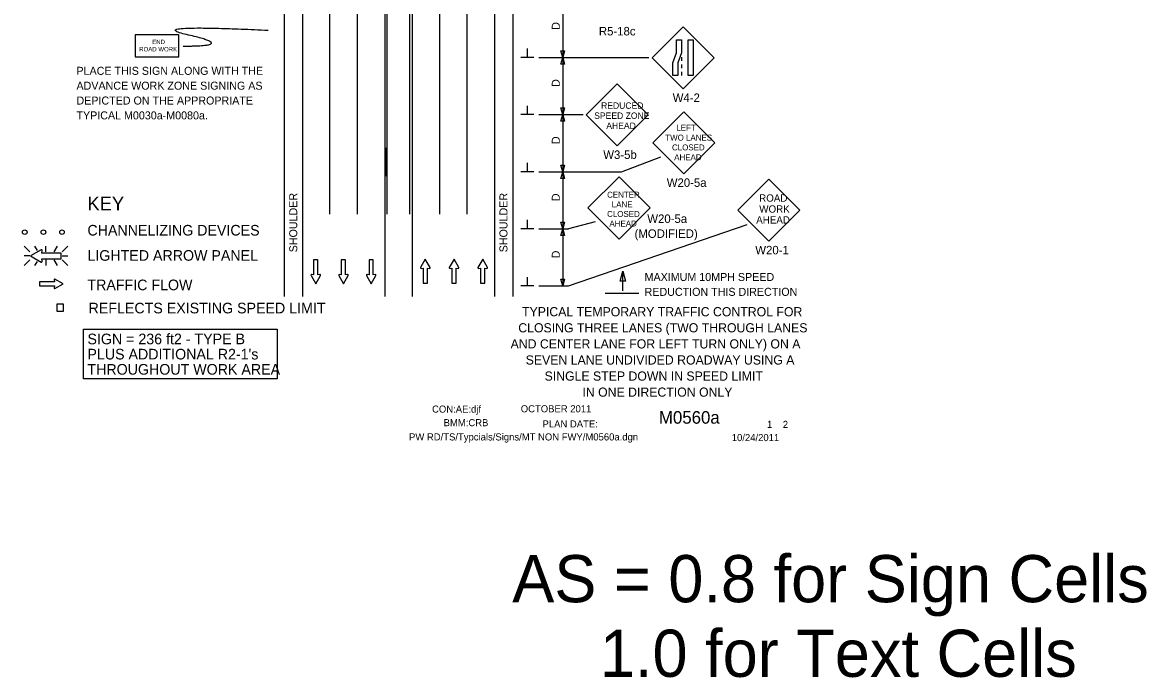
# Model space of a CAD drawing. Extents: x 16732 to 18475, y 5726 to 6929.
# Drawn here: x 16732 to 17716, y 5726 to 6300 of the extents above; entities that cross this region are included whole.
import ezdxf

# ---------------------------------------------------------------- set-up
doc = ezdxf.new("R2010")
doc.units = 0
for name, color, linetype in [('ALI_LEGAL_EX', 7, 'Continuous'), ('BORDER', 7, 'Continuous'), ('BORDER_SIGNAL_WO', 7, 'Continuous'), ('MT_SCRATCH_LEVEL_E', 7, 'Continuous'), ('PAVT_EDGE_EX', 7, 'Continuous'), ('TRAFFIC_SIGNS_PR', 7, 'Continuous'), ('TYPICAL_TEXT_DIMEN_EX', 7, 'Continuous'), ('TYPICAL_TEXT_DIMEN_PR', 7, 'Continuous')]:
    doc.layers.add(name, color=color, linetype=linetype)

msp = doc.modelspace()

# ---------------------------------------------------------------- linework, layer by layer
at = {"layer": 'ALI_LEGAL_EX'}
for p, q in [((17001.36, 6131.68), (17001.36, 6928.96)), ((17025.36, 6131.68), (17025.36, 6928.96)), ((17051.36, 6131.68), (17051.36, 6928.96)), ((17071.36, 6131.68), (17071.36, 6928.96)), ((17097.36, 6131.68), (17097.36, 6928.96)), ((17121.36, 6131.68), (17121.36, 6928.96))]:
    msp.add_line(p, q, dxfattribs=at)
for points in [[(17001.36, 6231.68), (17001.36, 6256.68)], [(17025.36, 6231.68), (17025.36, 6256.68)], [(17051.36, 6231.68), (17051.36, 6256.68)], [(17071.36, 6231.68), (17071.36, 6256.68)], [(17097.36, 6231.68), (17097.36, 6256.68)], [(17121.36, 6231.68), (17121.36, 6256.68)], [(17001.36, 6131.68), (17001.36, 6156.68)], [(17025.36, 6131.68), (17025.36, 6156.68)], [(17051.36, 6131.68), (17051.36, 6156.68)], [(17071.36, 6131.68), (17071.36, 6156.68)], [(17097.36, 6131.68), (17097.36, 6156.68)], [(17121.36, 6131.68), (17121.36, 6156.68)]]:
    msp.add_lwpolyline(points, dxfattribs=at)
at = {"layer": 'MT_SCRATCH_LEVEL_E'}
for p, q in [((16990.77, 6091.79), (16987.03, 6091.79)), ((16987.03, 6091.79), (16987.03, 6078.53)), ((16990.77, 6091.79), (16987.03, 6091.79)), ((16987.03, 6091.79), (16987.03, 6078.53)), ((16990.77, 6078.53), (16990.77, 6091.79)), ((16990.77, 6078.53), (16990.77, 6091.79)), ((17015.03, 6091.79), (17011.28, 6091.79)), ((17011.28, 6091.79), (17011.28, 6078.53)), ((17015.03, 6091.79), (17011.28, 6091.79)), ((17011.28, 6091.79), (17011.28, 6078.53)), ((17015.03, 6078.53), (17015.03, 6091.79)), ((17015.03, 6078.53), (17015.03, 6091.79)), ((17039.28, 6091.79), (17035.54, 6091.79)), ((17035.54, 6091.79), (17035.54, 6078.53)), ((17039.28, 6091.79), (17035.54, 6091.79)), ((17035.54, 6091.79), (17035.54, 6078.53)), ((17039.28, 6078.53), (17039.28, 6091.79)), ((17039.28, 6078.53), (17039.28, 6091.79)), ((17084.79, 6092.25), (17080.68, 6085.01)), ((17084.79, 6092.25), (17080.68, 6085.01)), ((17088.94, 6085.01), (17084.79, 6092.25)), ((17088.94, 6085.01), (17084.79, 6092.25)), ((17109.88, 6092.25), (17105.77, 6085.01)), ((17109.88, 6092.25), (17105.77, 6085.01)), ((17114.03, 6085.01), (17109.88, 6092.25)), ((17114.03, 6085.01), (17109.88, 6092.25)), ((17134.97, 6092.25), (17130.86, 6085.01)), ((17134.97, 6092.25), (17130.86, 6085.01)), ((17139.12, 6085.01), (17134.97, 6092.25)), ((17139.12, 6085.01), (17134.97, 6092.25)), ((16984.77, 6078.16), (16988.92, 6070.92)), ((16984.77, 6078.16), (16988.92, 6070.92)), ((16987.03, 6078.53), (16985.25, 6078.85)), ((16987.03, 6078.53), (16985.25, 6078.85)), ((16988.92, 6070.92), (16993.03, 6078.16)), ((16988.92, 6070.92), (16993.03, 6078.16)), ((16992.55, 6078.85), (16990.77, 6078.53)), ((16992.55, 6078.85), (16990.77, 6078.53)), ((17009.03, 6078.16), (17013.17, 6070.92)), ((17009.03, 6078.16), (17013.17, 6070.92)), ((17011.28, 6078.53), (17009.51, 6078.85)), ((17011.28, 6078.53), (17009.51, 6078.85)), ((17013.17, 6070.92), (17017.28, 6078.16)), ((17013.17, 6070.92), (17017.28, 6078.16)), ((17016.8, 6078.85), (17015.03, 6078.53)), ((17016.8, 6078.85), (17015.03, 6078.53)), ((17033.28, 6078.16), (17037.43, 6070.92)), ((17033.28, 6078.16), (17037.43, 6070.92)), ((17035.54, 6078.53), (17033.76, 6078.85)), ((17035.54, 6078.53), (17033.76, 6078.85)), ((17037.43, 6070.92), (17041.54, 6078.16)), ((17037.43, 6070.92), (17041.54, 6078.16)), ((17041.06, 6078.85), (17039.28, 6078.53)), ((17041.06, 6078.85), (17039.28, 6078.53)), ((17081.16, 6084.32), (17082.94, 6084.64)), ((17081.16, 6084.32), (17082.94, 6084.64)), ((17082.94, 6084.64), (17082.94, 6071.38)), ((17082.94, 6084.64), (17082.94, 6071.38)), ((17086.68, 6071.38), (17086.68, 6084.64)), ((17086.68, 6084.64), (17088.46, 6084.32)), ((17086.68, 6071.38), (17086.68, 6084.64)), ((17086.68, 6084.64), (17088.46, 6084.32)), ((17106.25, 6084.32), (17108.03, 6084.64)), ((17106.25, 6084.32), (17108.03, 6084.64)), ((17108.03, 6084.64), (17108.03, 6071.38)), ((17108.03, 6084.64), (17108.03, 6071.38)), ((17111.77, 6071.38), (17111.77, 6084.64)), ((17111.77, 6084.64), (17113.55, 6084.32)), ((17111.77, 6071.38), (17111.77, 6084.64)), ((17111.77, 6084.64), (17113.55, 6084.32)), ((17131.34, 6084.32), (17133.12, 6084.64)), ((17131.34, 6084.32), (17133.12, 6084.64)), ((17133.12, 6084.64), (17133.12, 6071.38)), ((17133.12, 6084.64), (17133.12, 6071.38)), ((17136.86, 6071.38), (17136.86, 6084.64)), ((17136.86, 6084.64), (17138.64, 6084.32)), ((17136.86, 6071.38), (17136.86, 6084.64)), ((17136.86, 6084.64), (17138.64, 6084.32)), ((16760.32, 6072.68), (16747.06, 6072.68)), ((16747.06, 6072.68), (16747.06, 6068.94)), ((16760.32, 6072.68), (16747.06, 6072.68)), ((16747.06, 6072.68), (16747.06, 6068.94)), ((16747.06, 6068.94), (16760.32, 6068.94)), ((16747.06, 6068.94), (16760.32, 6068.94)), ((16760, 6074.45), (16760.32, 6072.68)), ((16760, 6074.45), (16760.32, 6072.68)), ((16760.32, 6068.94), (16760, 6067.16)), ((16760.32, 6068.94), (16760, 6067.16)), ((16767.93, 6070.83), (16760.69, 6074.94)), ((16767.93, 6070.83), (16760.69, 6074.94)), ((16760.69, 6066.68), (16767.93, 6070.83)), ((16760.69, 6066.68), (16767.93, 6070.83)), ((17082.94, 6071.38), (17086.68, 6071.38)), ((17082.94, 6071.38), (17086.68, 6071.38)), ((17108.03, 6071.38), (17111.77, 6071.38)), ((17108.03, 6071.38), (17111.77, 6071.38)), ((17133.12, 6071.38), (17136.86, 6071.38)), ((17133.12, 6071.38), (17136.86, 6071.38))]:
    msp.add_line(p, q, dxfattribs=at)
for centre, start, end in [((16985.18, 6078.38), 80.03619, 209.77312), ((16985.18, 6078.38), 80.03619, 209.77312), ((16992.62, 6078.39), 330.42484, 99.96381), ((16992.62, 6078.39), 330.42484, 99.96381), ((17009.44, 6078.38), 80.03619, 209.77312), ((17009.44, 6078.38), 80.03619, 209.77312), ((17016.88, 6078.39), 330.42484, 99.96381), ((17016.88, 6078.39), 330.42484, 99.96381), ((17033.69, 6078.38), 80.03619, 209.77312), ((17033.69, 6078.38), 80.03619, 209.77312), ((17041.13, 6078.39), 330.42484, 99.96381), ((17041.13, 6078.39), 330.42484, 99.96381), ((17081.09, 6084.78), 150.42484, 279.96381), ((17081.09, 6084.78), 150.42484, 279.96381), ((17088.53, 6084.78), 260.03619, 29.77312), ((17088.53, 6084.78), 260.03619, 29.77312), ((17106.18, 6084.78), 150.42484, 279.96381), ((17106.18, 6084.78), 150.42484, 279.96381), ((17113.62, 6084.78), 260.03619, 29.77312), ((17113.62, 6084.78), 260.03619, 29.77312), ((17131.27, 6084.78), 150.42484, 279.96381), ((17131.27, 6084.78), 150.42484, 279.96381), ((17138.71, 6084.78), 260.03619, 29.77312), ((17138.71, 6084.78), 260.03619, 29.77312), ((16760.46, 6074.53), 60.42484, 189.96381), ((16760.46, 6074.53), 60.42484, 189.96381), ((16760.46, 6067.09), 170.03619, 299.77312), ((16760.46, 6067.09), 170.03619, 299.77312)]:
    msp.add_arc(centre, 0.463, start, end, dxfattribs=at)
at = {"layer": 'PAVT_EDGE_EX'}
for p, q in [((16961.36, 6924.76), (16961.36, 6059.7)), ((16977.36, 6924.76), (16977.36, 6059.7)), ((17049.36, 6924.76), (17049.36, 6059.7)), ((17073.36, 6924.76), (17073.36, 6059.7)), ((17145.36, 6924.76), (17145.36, 6059.7)), ((17161.36, 6924.76), (17161.36, 6059.7))]:
    msp.add_line(p, q, dxfattribs=at)
for points in [[(17025.36, 6164.93), (17025.36, 6189.93)], [(17050.36, 6164.93), (17050.36, 6189.93)]]:
    msp.add_lwpolyline(points, dxfattribs=at)
at = {"layer": 'TRAFFIC_SIGNS_PR'}
for p, q in [((17310.3, 6295.68), (17283.14, 6268.53)), ((17337.45, 6268.53), (17310.3, 6295.68)), ((17283.14, 6268.53), (17310.3, 6241.38)), ((17309.05, 6269.02), (17309.05, 6265.82)), ((17310.3, 6241.38), (17337.45, 6268.53)), ((17309.05, 6262.62), (17309.05, 6259.42)), ((17309.05, 6256.22), (17309.05, 6253.02)), ((17252.53, 6245.81), (17225.38, 6218.66)), ((17279.68, 6218.66), (17252.53, 6245.81)), ((17225.38, 6218.66), (17252.53, 6191.5)), ((17252.53, 6191.5), (17279.68, 6218.66)), ((17310.9, 6221.38), (17283.74, 6194.22)), ((17338.05, 6194.22), (17310.9, 6221.38)), ((17283.74, 6194.22), (17310.9, 6167.07)), ((17310.9, 6167.07), (17338.05, 6194.22)), ((17254.27, 6164.31), (17227.12, 6137.16)), ((17281.42, 6137.16), (17254.27, 6164.31)), ((17385.35, 6162.3), (17358.2, 6135.15)), ((17412.5, 6135.15), (17385.35, 6162.3)), ((17227.12, 6137.16), (17254.27, 6110)), ((17254.27, 6110), (17281.42, 6137.16)), ((17358.2, 6135.15), (17385.35, 6108)), ((17385.35, 6108), (17412.5, 6135.15)), ((16733.68, 6103.69), (16738.62, 6098.76)), ((16745.44, 6099.87), (16743.24, 6103.7)), ((16752.76, 6098.76), (16752.76, 6103.7)), ((16760, 6098.76), (16762.85, 6103.7)), ((16766.91, 6098.76), (16771.85, 6103.7)), ((16738.62, 6095.21), (16733.68, 6095.21)), ((16733.68, 6086.72), (16738.62, 6091.65)), ((16743.19, 6086.72), (16745.31, 6090.38)), ((16752.76, 6091.65), (16752.76, 6086.72)), ((16762.89, 6086.72), (16760.04, 6091.65)), ((16766.91, 6095.21), (16771.85, 6095.21)), ((16766.91, 6091.65), (16771.85, 6086.71))]:
    msp.add_line(p, q, dxfattribs=at)
for points in [[(16830.82, 6269.48), (16869.22, 6269.48), (16869.22, 6288.68), (16830.82, 6288.68)], [(17309.05, 6284.27), (17309.05, 6273.08), (17305.7, 6264.2), (17305.7, 6253.02), (17301.21, 6253.02), (17301.21, 6264.2), (17304.56, 6273.08), (17304.56, 6284.27)], [(17319.18, 6284.27), (17319.18, 6253.02), (17314.69, 6253.02), (17314.69, 6284.27)], [(16762.47, 6046.77), (16768.06, 6046.77), (16768.06, 6052.94), (16762.47, 6052.94)]]:
    msp.add_lwpolyline(points, close=True, dxfattribs=at)
for points in [[(16748.69, 6100.48), (16739.4, 6095.21), (16748.69, 6089.88)], [(16749.57, 6090.51), (16749.17, 6092.78), (16766.18, 6092.78), (16766.18, 6097.58), (16749.17, 6097.58), (16749.57, 6099.86)]]:
    msp.add_lwpolyline(points, dxfattribs=at)
for centre in [(16734.3, 6115.98), (16750.6, 6115.98), (16766.9, 6115.98)]:
    msp.add_circle(centre, 2, dxfattribs=at)
for centre, radius, start, end in [((16748.98, 6099.96), 0.598, 350.73078, 118.89165), ((16748.98, 6090.41), 0.597, 241.48329, 9.95933)]:
    msp.add_arc(centre, radius, start, end, dxfattribs=at)
msp.add_open_spline([(16872.81, 6278.85), (16920.05, 6278.85), (16835.03, 6298.2), (16947.32, 6292.71)], degree=2, dxfattribs=at)
at = {"layer": 'TYPICAL_TEXT_DIMEN_EX'}
msp.add_lwpolyline([(16785.8, 6031.01), (16955.01, 6031.01), (16955.01, 5987.65), (16785.8, 5987.65)], close=True, dxfattribs=at)
at = {"layer": 'TYPICAL_TEXT_DIMEN_PR'}
for p, q in [((17204.99, 6318.89), (17204.99, 6268.89)), ((17174.11, 6268.89), (17174.11, 6276.68)), ((17179.74, 6268.89), (17168.49, 6268.89)), ((17183.99, 6268.89), (17280.24, 6268.89)), ((17204.99, 6268.89), (17203.42, 6274.75)), ((17203.42, 6274.75), (17204.99, 6274.75)), ((17203.42, 6263.03), (17204.99, 6268.89)), ((17204.99, 6274.75), (17206.56, 6274.75)), ((17206.56, 6274.75), (17204.99, 6268.89)), ((17204.99, 6268.89), (17204.99, 6218.89)), ((17204.99, 6268.89), (17206.56, 6263.03)), ((17204.99, 6263.03), (17203.42, 6263.03)), ((17206.56, 6263.03), (17204.99, 6263.03)), ((17174.11, 6218.89), (17174.11, 6226.68)), ((17179.74, 6218.89), (17168.49, 6218.89)), ((17183.99, 6218.89), (17222.99, 6218.89)), ((17204.99, 6218.89), (17203.42, 6224.75)), ((17203.42, 6224.75), (17204.99, 6224.75)), ((17203.42, 6213.03), (17204.99, 6218.89)), ((17204.99, 6224.75), (17206.56, 6224.75)), ((17206.56, 6224.75), (17204.99, 6218.89)), ((17204.99, 6218.89), (17204.99, 6168.89)), ((17204.99, 6218.89), (17206.56, 6213.03)), ((17204.99, 6213.03), (17203.42, 6213.03)), ((17206.56, 6213.03), (17204.99, 6213.03)), ((17174.11, 6168.89), (17174.11, 6176.68)), ((17256.39, 6168.89), (17290.92, 6181.99)), ((17179.74, 6168.89), (17168.49, 6168.89)), ((17183.99, 6168.89), (17256.39, 6168.89)), ((17204.99, 6168.89), (17203.42, 6174.75)), ((17203.42, 6174.75), (17204.99, 6174.75)), ((17203.42, 6163.03), (17204.99, 6168.89)), ((17204.99, 6174.75), (17206.56, 6174.75)), ((17206.56, 6174.75), (17204.99, 6168.89)), ((17204.99, 6168.89), (17204.99, 6118.89)), ((17204.99, 6168.89), (17206.56, 6163.03)), ((17204.99, 6163.03), (17203.42, 6163.03)), ((17206.56, 6163.03), (17204.99, 6163.03)), ((17179.74, 6118.89), (17168.49, 6118.89)), ((17174.11, 6118.89), (17174.11, 6126.68)), ((17183.99, 6118.89), (17209.99, 6118.89)), ((17204.99, 6118.89), (17203.42, 6124.75)), ((17203.42, 6124.75), (17204.99, 6124.75)), ((17203.42, 6113.03), (17204.99, 6118.89)), ((17204.99, 6124.75), (17206.56, 6124.75)), ((17206.56, 6124.75), (17204.99, 6118.89)), ((17204.99, 6118.89), (17204.99, 6068.89)), ((17204.99, 6118.89), (17206.56, 6113.03)), ((17233.34, 6124.92), (17209.99, 6118.89)), ((17209.99, 6068.89), (17366.27, 6122.75)), ((17204.99, 6113.03), (17203.42, 6113.03)), ((17206.56, 6113.03), (17204.99, 6113.03)), ((17255.14, 6073.01), (17257.5, 6081.81)), ((17257.5, 6064.68), (17257.5, 6081.81)), ((17257.5, 6081.81), (17259.86, 6073.01)), ((17179.74, 6068.89), (17168.49, 6068.89)), ((17174.11, 6068.89), (17174.11, 6076.68)), ((17183.99, 6068.89), (17209.99, 6068.89)), ((17204.99, 6068.89), (17203.42, 6074.75)), ((17203.42, 6074.75), (17204.99, 6074.75)), ((17204.99, 6074.75), (17206.56, 6074.75)), ((17206.56, 6074.75), (17204.99, 6068.89)), ((17257.5, 6073.01), (17255.14, 6073.01)), ((17259.86, 6073.01), (17257.5, 6073.01)), ((17271.67, 6062.18), (17242.23, 6062.18))]:
    msp.add_line(p, q, dxfattribs=at)

# ---------------------------------------------------------------- texts
at = {"layer": 'BORDER'}
for s, height, p in [('TYPICAL TEMPORARY TRAFFIC CONTROL FOR', 8.0313, (17169.43, 6042.37)), ('CLOSING THREE LANES (TWO THROUGH LANES', 8.0313, (17166.13, 6028.29)), ('AND CENTER LANE FOR LEFT TURN ONLY) ON A', 8.0313, (17159.4, 6014.22)), ('SEVEN LANE UNDIVIDED ROADWAY USING A', 8.0313, (17172.62, 6000.14)), ('SINGLE STEP DOWN IN SPEED LIMIT', 8.0313, (17189.14, 5986.06)), ('IN ONE DIRECTION ONLY', 8.0313, (17222.25, 5971.99)), ('PLAN DATE:', 6.2, (17187.35, 5945.07))]:
    msp.add_text(s, height=height, dxfattribs=at).set_placement(p)
at = {"layer": 'BORDER_SIGNAL_WO'}
for s, height, p in [('CON:AE:djf', 6.2, (17090.69, 5958.06)), ('    OCTOBER 2011    ', 6.2, (17159.08, 5958.34)), ('BMM:CRB   ', 6.2, (17100.81, 5946.17)), ('    M0560a   ', 11, (17272.86, 5948.38)), (' 1    2 ', 6.2, (17381.45, 5944.7)), ('PW RD/TS/Typcials/Signs/MT NON FWY/M0560a.dgn    ', 6.2, (17070.55, 5933.71)), ('10/24/2011    ', 6.2, (17352.93, 5933.13)), ('AS = 0.8 for Sign Cells', 41.2877, (17160.83, 5792.11)), ('     1.0 for Text Cells', 41.2877, (17160.83, 5726.82))]:
    msp.add_text(s, height=height, dxfattribs=at).set_placement(p)
at = {"layer": 'TRAFFIC_SIGNS_PR'}
for s, height, p in [('R5-18c', 7.44, (17236.65, 6288.18)), ('ROAD WORK', 3.831, (16834.43, 6274.22)), ('END', 3.831, (16845.82, 6280.61)), ('PLACE THIS SIGN ALONG WITH THE', 7, (16779.54, 6253.7)), ('ADVANCE WORK ZONE SIGNING AS', 7, (16779.54, 6240.7)), ('W4-2', 7.44, (17301.25, 6229.94)), ('DEPICTED ON THE APPROPRIATE', 7, (16779.54, 6227.7)), ('REDUCED', 5.6, (17238.59, 6223.97)), ('TYPICAL M0030a-M0080a.', 7, (16779.54, 6214.7)), ('SPEED ZONE', 5.6, (17232.58, 6215.16)), ('AHEAD', 5.6, (17243.14, 6206.36)), ('LEFT', 5.2, (17304.43, 6204.76)), ('TWO LANES', 5.2, (17294.76, 6196.16)), ('W3-5b', 7.44, (17240.48, 6180.06)), ('CLOSED', 5.2, (17300.61, 6187.56)), ('AHEAD', 5.2, (17302.55, 6178.96)), ('W20-5a', 7.44, (17296.04, 6155.63)), ('CENTER', 5.2, (17243.84, 6146.16)), ('ROAD', 6.4, (17376.89, 6142.69)), ('LANE', 5.2, (17247.92, 6137.76)), ('WORK', 6.4, (17377, 6133.09)), ('CLOSED', 5.2, (17243.85, 6129.36)), ('W20-5a', 7.44, (17279.01, 6124.07)), ('AHEAD', 6.4, (17374.31, 6123.49)), ('AHEAD', 5.2, (17245.87, 6120.96)), ('(MODIFIED)', 7.44, (17267.87, 6111.03)), ('W20-1', 7.44, (17373.52, 6096.56))]:
    msp.add_text(s, height=height, dxfattribs=at).set_placement(p)
at = {"layer": 'TYPICAL_TEXT_DIMEN_EX'}
for s, height, p in [('KEY', 12, (16789.14, 6135.09)), ('CHANNELIZING DEVICES', 9.3, (16789.14, 6113.04)), ('LIGHTED ARROW PANEL', 9.3, (16789.14, 6090.99)), ('TRAFFIC FLOW', 9.3, (16789.14, 6065.19)), ('REFLECTS EXISTING SPEED LIMIT', 9.3, (16790.15, 6044.93)), ('SIGN = 236 ft2 - TYPE B', 9.3, (16789.14, 6017.9)), ("PLUS ADDITIONAL R2-1's", 9.3, (16789.14, 6004.6)), ('THROUGHOUT WORK AREA', 9.3, (16789.14, 5991.3))]:
    msp.add_text(s, height=height, dxfattribs=at).set_placement(p)
at = {"layer": 'TYPICAL_TEXT_DIMEN_PR'}
for s, p in [('D', (17202.43, 6293.11)), ('D', (17202.43, 6243.11)), ('D', (17202.43, 6193.11)), ('SHOULDER', (16972.73, 6098.36)), ('SHOULDER', (17156.64, 6098.36)), ('D', (17202.43, 6143.11)), ('D', (17202.43, 6093.11))]:
    msp.add_text(s, height=7, rotation=90, dxfattribs=at).set_placement(p)
for s, p in [('MAXIMUM 10MPH SPEED', (17276.65, 6073.28)), ('REDUCTION THIS DIRECTION', (17276.65, 6060.28))]:
    msp.add_text(s, height=7, dxfattribs=at).set_placement(p)

doc.saveas('drawing.dxf')
